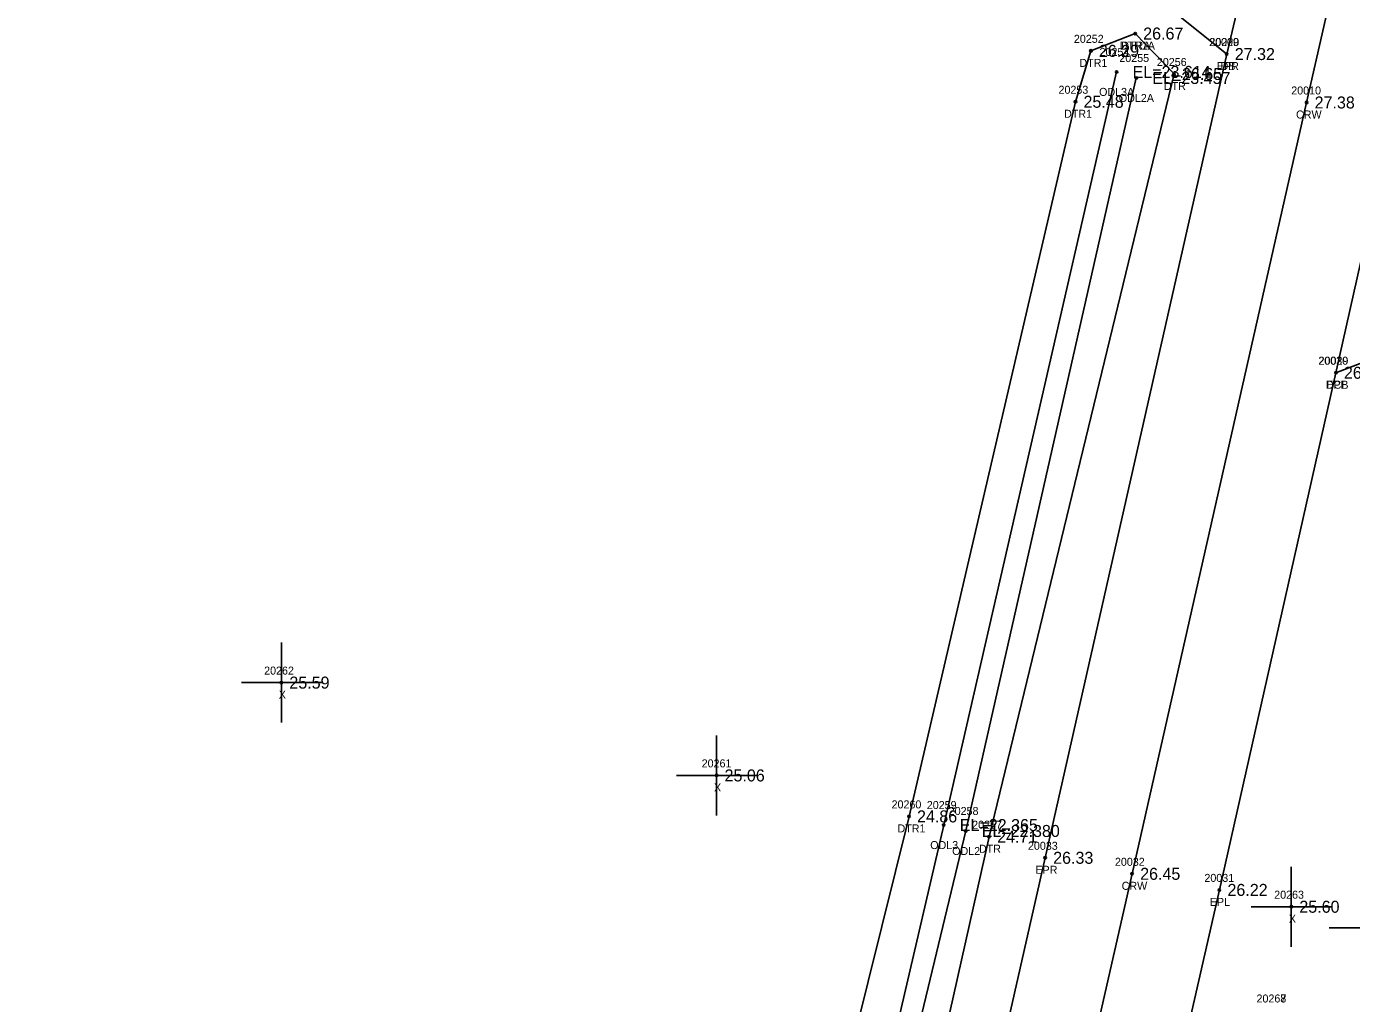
# Model space of a CAD drawing. Extents: x 2655177 to 2656219, y 761780 to 764748.
# Drawn here: x 2655847.5 to 2656013, y 764411.4 to 764533.5 of the extents above; entities that cross this region are included whole.
import ezdxf

# ---------------------------------------------------------------- set-up
doc = ezdxf.new("R2010")
doc.units = 0
for name, color, linetype in [('RD_DTM_BkLn1', 7, 'Continuous'), ('RD_EX_Conc', 7, 'Continuous'), ('RD_EX_Conc_txCode', 7, 'Continuous'), ('RD_EX_Driveway', 7, 'Continuous'), ('RD_EX_Driveway_txCode', 7, 'Continuous'), ('RD_EX_H2O', 7, 'Continuous'), ('RD_EX_H2O_txCode', 7, 'Continuous'), ('RD_EX_Misc', 7, 'Continuous'), ('RD_EX_Misc_txCode', 7, 'Continuous'), ('RD_EX_Road', 7, 'Continuous'), ('RD_EX_Road_txCode', 7, 'Continuous'), ('RD_EX_TX_Conc_ELEV', 7, 'Continuous'), ('RD_EX_TX_Driveway_ELEV', 7, 'Continuous'), ('RD_EX_TX_H2O_ELEV', 7, 'Continuous'), ('RD_EX_TX_Misc_ELEV', 7, 'Continuous'), ('RD_EX_TX_Road_ELEV', 7, 'Continuous'), ('RD_HC_Survey_ELEV', 7, 'Continuous'), ('RD_HC_Survey_txCode', 7, 'Continuous'), ('RD_SMD_Locator', 7, 'Continuous')]:
    doc.layers.add(name, color=color, linetype=linetype)

msp = doc.modelspace()

# ---------------------------------------------------------------- linework, layer by layer
at = {"layer": 'RD_DTM_BkLn1'}
msp.add_lwpolyline([(2656052.36, 764720.46), (2656029.22, 764619.66), (2656007.41, 764523.97), (2655985.61, 764427.64), (2655963.53, 764330.64), (2655941.2, 764233.56), (2655920.06, 764141.06), (2655898.52, 764047.86), (2655877.71, 763954.88), (2655855.89, 763859.81), (2655834.07, 763763.97), (2655811.81, 763666.79), (2655790.48, 763573.22), (2655769.27, 763483.63), (2655747.64, 763389.32), (2655725.4, 763293.96), (2655721.51, 763275.9)], dxfattribs=at)
at = {"layer": 'RD_EX_Conc'}
msp.add_lwpolyline([(2656094.12, 764463.32), (2656085.97, 764470.54), (2656075.61, 764477.32), (2656065.58, 764481.79), (2656024.11, 764493.18), (2656018.85, 764493.22), (2656011.07, 764490.22)], dxfattribs=at)
at = {"layer": 'RD_EX_Driveway'}
msp.add_lwpolyline([(2655881.18, 764579.69), (2655985.53, 764539.6), (2655997.43, 764530.02)], dxfattribs=at)
at = {"layer": 'RD_EX_H2O'}
for points in [[(2655985.99, 764532.58), (2655990.84, 764527.53), (2655967.74, 764432.27), (2655946, 764335.4), (2655922.66, 764238.07), (2655902.06, 764145.42), (2655879.59, 764053.25), (2655859.1, 763959.14), (2655841.15, 763874.16), (2655837.57, 763865.39), (2655829.11, 763865.29), (2655761.29, 763886.78)], [(2655985.99, 764532.58), (2655980.45, 764530.42), (2655978.53, 764524.06), (2655957.73, 764434.81), (2655933.82, 764338.64), (2655911.79, 764241.24), (2655890.59, 764146.77), (2655869.91, 764054.39), (2655847.97, 763961.11)], [(2655983.66, 764527.79), (2655962.07, 764433.73), (2655939.64, 764337.32), (2655916.77, 764240.59), (2655893.69, 764145.91), (2655873.09, 764053.84), (2655852.96, 763960.1)], [(2655986.13, 764527.03), (2655964.81, 764432.99), (2655941.76, 764337.09), (2655920.19, 764238.99), (2655899.24, 764145.84), (2655875.75, 764053.31), (2655856.78, 763959.16), (2655834.97, 763871.07)]]:
    msp.add_lwpolyline(points, dxfattribs=at)
at = {"layer": 'RD_EX_Misc'}
for p, q in [((2655879.3, 764446.52), (2655879.3, 764456.52)), ((2655874.3, 764451.52), (2655884.3, 764451.52)), ((2655933.68, 764434.93), (2655933.68, 764444.93)), ((2655928.68, 764439.93), (2655938.68, 764439.93)), ((2656005.5, 764418.53), (2656005.5, 764428.53)), ((2656000.5, 764423.53), (2656010.5, 764423.53)), ((2656010.23, 764420.91), (2656020.23, 764420.91))]:
    msp.add_line(p, q, dxfattribs=at)
at = {"layer": 'RD_EX_Road'}
for points in [[(2656041.72, 764723.31), (2656018.5, 764622.03), (2656002.75, 764552.49), (2655997.43, 764530.02), (2655974.74, 764429.64), (2655952.97, 764333.57), (2655930.52, 764235.7), (2655909.18, 764142.93), (2655887.93, 764050.57), (2655866.91, 763957.26), (2655846.82, 763869.53), (2655845.21, 763862.22), (2655839.99, 763839.71), (2655823.38, 763766.66), (2655801.33, 763669.93), (2655780.03, 763576.53), (2655774.26, 763551.85), (2655771.37, 763539.86), (2655759.09, 763486.9), (2655736.94, 763391.72), (2655715.19, 763296.77), (2655711.35, 763278.45)], [(2656062.87, 764717.57), (2656039.84, 764617.04), (2656035.41, 764597.94), (2656033.38, 764589.18), (2656018.27, 764522.6), (2656017.22, 764517.64), (2656011.07, 764490.22), (2655996.52, 764425.63), (2655974.03, 764327.02), (2655960.71, 764269.34), (2655951.96, 764231.59), (2655930.84, 764138.62), (2655926.81, 764121.01)]]:
    msp.add_lwpolyline(points, dxfattribs=at)
at = {"layer": 'RD_SMD_Locator'}
for centre in [(2655985.99, 764532.58), (2655985.99, 764532.58), (2655980.45, 764530.42), (2655997.43, 764530.02), (2655997.43, 764530.02), (2655983.66, 764527.79), (2655986.13, 764527.03), (2655990.84, 764527.53), (2655978.53, 764524.06), (2656007.41, 764523.97), (2656011.07, 764490.22), (2656011.07, 764490.22), (2655879.3, 764451.52), (2655933.68, 764439.93), (2655957.73, 764434.81), (2655962.07, 764433.73), (2655964.81, 764432.99), (2655967.74, 764432.27), (2655974.74, 764429.64), (2655985.61, 764427.64), (2655996.52, 764425.63), (2656005.5, 764423.53)]:
    msp.add_circle(centre, 0.15, dxfattribs=at)

# ---------------------------------------------------------------- texts
at = {"layer": 'RD_EX_Conc_txCode'}
for s, p in [('20029', (2656008.91, 764491.22)), ('DCB', (2656009.82, 764488.22))]:
    msp.add_text(s, height=1, dxfattribs=at).set_placement(p)
at = {"layer": 'RD_EX_Driveway_txCode'}
for s, p in [('20220', (2655995.27, 764531.02)), ('DB', (2655996.65, 764528.02))]:
    msp.add_text(s, height=1, dxfattribs=at).set_placement(p)
at = {"layer": 'RD_EX_H2O_txCode'}
for s, p in [('20252', (2655978.33, 764531.42)), ('DTR1A', (2655984.07, 764530.58)), ('DTRA', (2655984.24, 764530.58)), ('DTR1', (2655979.02, 764528.42)), ('20254', (2655981.54, 764529.79)), ('20255', (2655984.01, 764529.03)), ('20256', (2655988.7, 764528.53)), ('DTR', (2655989.57, 764525.53)), ('20253', (2655976.41, 764525.06)), ('ODL3A', (2655981.48, 764524.79)), ('ODL2A', (2655983.95, 764524.03)), ('DTR1', (2655977.1, 764522.06)), ('20260', (2655955.55, 764435.81)), ('20259', (2655959.95, 764435.73)), ('20258', (2655962.69, 764434.99)), ('DTR1', (2655956.29, 764432.81)), ('20257', (2655965.62, 764433.27)), ('ODL3', (2655960.38, 764430.73)), ('ODL2', (2655963.12, 764429.99)), ('DTR', (2655966.47, 764430.27)), ('20267', (2656001.15, 764411.57)), ('20268', (2656001.15, 764411.57))]:
    msp.add_text(s, height=1, dxfattribs=at).set_placement(p)
at = {"layer": 'RD_EX_Misc_txCode'}
for s, p in [('20262', (2655877.15, 764452.52)), ('X', (2655878.98, 764449.52)), ('20261', (2655931.82, 764440.93)), ('X', (2655933.36, 764437.93)), ('20263', (2656003.36, 764424.53)), ('X', (2656005.19, 764421.53))]:
    msp.add_text(s, height=1, dxfattribs=at).set_placement(p)
at = {"layer": 'RD_EX_Road_txCode'}
for s, p in [('20009', (2655995.23, 764531.02)), ('EPR', (2655996.2, 764528.02)), ('20030', (2656008.87, 764491.22)), ('EPL', (2656009.87, 764488.22)), ('20033', (2655972.59, 764430.64)), ('EPR', (2655973.52, 764427.64)), ('20031', (2655994.64, 764426.63)), ('EPL', (2655995.31, 764423.63))]:
    msp.add_text(s, height=1, dxfattribs=at).set_placement(p)
at = {"layer": 'RD_EX_TX_Conc_ELEV'}
msp.add_text('26.91', height=1.5, dxfattribs=at).set_placement((2656012.07, 764489.47))
at = {"layer": 'RD_EX_TX_Driveway_ELEV'}
msp.add_text('27.32', height=1.5, dxfattribs=at).set_placement((2655998.43, 764529.27))
at = {"layer": 'RD_EX_TX_H2O_ELEV'}
for s, p in [('26.67', (2655986.99, 764531.83)), ('26.67', (2655986.99, 764531.83)), ('26.29', (2655981.45, 764529.67)), ('EL=23.614', (2655985.66, 764527.04)), ('EL=23.457', (2655988.13, 764526.28)), ('26.65', (2655991.84, 764526.78)), ('25.48', (2655979.53, 764523.31)), ('24.86', (2655958.73, 764434.06)), ('EL=22.365', (2655964.07, 764432.98)), ('EL=22.380', (2655966.81, 764432.24)), ('24.71', (2655968.74, 764431.52))]:
    msp.add_text(s, height=1.5, dxfattribs=at).set_placement(p)
at = {"layer": 'RD_EX_TX_Misc_ELEV'}
for s, p in [('25.59', (2655880.3, 764450.77)), ('25.06', (2655934.68, 764439.18)), ('25.60', (2656006.5, 764422.78))]:
    msp.add_text(s, height=1.5, dxfattribs=at).set_placement(p)
at = {"layer": 'RD_EX_TX_Road_ELEV'}
for s, p in [('27.32', (2655998.43, 764529.27)), ('26.91', (2656012.07, 764489.47)), ('26.33', (2655975.74, 764428.89)), ('26.22', (2655997.52, 764424.88))]:
    msp.add_text(s, height=1.5, dxfattribs=at).set_placement(p)
at = {"layer": 'RD_HC_Survey_ELEV'}
for s, p in [('27.38', (2656008.41, 764523.22)), ('26.45', (2655986.61, 764426.89))]:
    msp.add_text(s, height=1.5, dxfattribs=at).set_placement(p)
at = {"layer": 'RD_HC_Survey_txCode'}
for s, p in [('20010', (2656005.49, 764524.97)), ('CRW', (2656006.09, 764521.97)), ('20032', (2655983.46, 764428.64)), ('CRW', (2655984.3, 764425.64))]:
    msp.add_text(s, height=1, dxfattribs=at).set_placement(p)

doc.saveas('drawing.dxf')
